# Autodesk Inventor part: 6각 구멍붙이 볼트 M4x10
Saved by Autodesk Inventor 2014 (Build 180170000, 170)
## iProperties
Created: 2026-04
Part Number: 6각 구멍붙이 볼트 M4x10
Material: 강철, 연강
Document SubType Name: Modeling
Designer: dg
Density: 7.86 g/cm^3
Appearance: 강철
Mass: 2.0371 g
Surface Area: 3.0572 cm^2
Volume: 0.259174 cm^3
Author: jhkim
Description: 6각머리 태핑 나사
Creation Date: 2026-03-27
Sending System: Autodesk Inventor 2026
Preprocessor: ST-DEVELOPER v20.1
Author: dg
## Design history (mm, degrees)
node "6각 구멍붙이 볼트 M4x101"
body "Solid1"
node "기준1"
